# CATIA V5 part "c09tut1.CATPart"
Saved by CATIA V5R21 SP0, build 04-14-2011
Part number: c09_tut1
Bounding box of the stored display mesh (mm): x -75 to 138.5, y -40 to 40, z 0 to 100
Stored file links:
  D:\CATIA V5R21 E-RESOURCES\CATIA-V5R21\catia-v5r21-prt\c09-catia-v5r20-prt\c09-catia-v5r21-tut01.CATPart
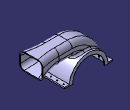
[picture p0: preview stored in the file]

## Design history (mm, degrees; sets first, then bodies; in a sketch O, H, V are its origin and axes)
Body1 (main body)
  Sketch1 on zx-plane, origin (0, 0, 0), H (-1, 0, 0), V (0, 0, 1)
    arc A1 centre (0, 0) radius 60 from (60, 0) to (-60, 0) ccw
    point P1 (-60, 0)
    point P2 (60, 0)
    line L1 (-60, 0) -> (60, 0)
    radius A1 = 60
    coincidence: P1 H, P2 H
    horizontal: L1 H
  Pad1: profile Sketch1, direction (0, 1, 0), length 40, mirrored extent
  Sketch2 on zx-plane, origin (0, 0, 0), H (-1, 0, 0), V (0, 0, 1)
    point P1 (-81.5, 100)
    line L1 (-81.5, 100) -> (-40, 100)
    arc A1 centre (-40, 0) radius 100 from (-40, 100) to (60, 0) cw
    point P4 (60, 0)
    reference projected arc E1 centre (0, 0) radius 60 from (60, 0) to (-60, 0) ccw from edge [face of Pad1 from Sketch1.A1 | end face of Pad1]
    reference projected arc E2 centre (0, 0) radius 60 from (60, 0) to (-60, 0) ccw from edge [face of Pad1 from Sketch1.A1 | end face of Pad1]
    radius A1 = 100
    distance V P1 = 81.5
    distance H L1 = 100
    horizontal: L1 H
    tangency: A1 L1, A1 E2
    coincidence: P4 E1
  Plane1: type Normal, Curve Sketch2, RefPoint Sketch2.P1
  Sketch3 on Plane1, origin (81.5, 0, 0), H (0, 1, 0), V (0, 0, 1)
    line L1 (-28.75, 100) -> (28.75, 100)
    line L2 (28.75, 100) -> (28.75, 58)
    line L3 (28.75, 58) -> (-28.75, 58)
    line L4 (-28.75, 58) -> (-28.75, 100)
    reference projected point E1 (0, 100) from Sketch2.P1
    reference projected point E2 (0, 100) from Sketch2.P1
    length L1 = 57.5
    length L2 = 42
    distance E1 L4 = 28.75
    horizontal: L1 H, L3 H
    vertical: L2 V, L4 V
    coincidence: L1 E2
  Rib1: profile Sketch3, centre curve Sketch2
  Plane2: type Offset, RefPlane face of Rib1, Offset 57, reversed
  Sketch4 on Plane2, origin (138.5, 0, 0), H (0, -1, 0), V (0, 0, 1)
    line L1 (36.25, 100) -> (36.25, 47.5)
    line L2 (36.25, 47.5) -> (-36.25, 47.5)
    line L3 (-36.25, 47.5) -> (-36.25, 100)
    line L4 (-36.25, 100) -> (36.25, 100)
    length L3 = 52.5
    distance V L3 = 36.25
    distance L3 L1 = 72.5
    distance H L4 = 100
    horizontal: L2 H
    vertical: L1 V, L3 V
  Loft1: solid, Sections ({boundary Boundary {extract ExtractElem face of Rib1}}; Sketch4), StartFace face of Rib1
  Fillet1: radius 15, on edge [face of Loft1 | face of Rib1]; edge [face of Rib1 | face of Rib1] (x8); edge [face of Loft1 | face of Loft1] (x2); edge [face of Rib1 | face of Loft1]
  Shell1: ExtOffset 0, Face (face of Loft1; face of Rib1), IntOffset 2.5
  Fillet2: radius 5, on edge [face of Pad1 from Sketch1.A1 | face of Fillet1]; edge [face of Shell1 | face of Shell1]
  Sketch5 on end face of Pad1, origin (0, 40, 0), H (-1, 0, 0), V (0, 0, 1)
    arc A1 centre (0, 0) radius 50 from (50, 0) to (-50, 0) ccw
    point P1 (-50, 0)
    point P2 (50, 0)
    line L1 (-50, 0) -> (50, 0)
    radius A1 = 50
    coincidence: P1 H, P2 H
    horizontal: L1 H
  Pocket1: profile Sketch5, direction (0, -1, 0), through (limit type 6)
  Sketch6 on start face of Pad1, origin (0, -40, 0), H (1, 0, 0), V (0, 0, 1)
    arc A1 centre (0, 0) radius 15 from (15, 0) to (-15, 0) ccw
    point P1 (15, 0)
    point P2 (-15, 0)
    line L1 (-15, 0) -> (15, 0)
    radius A1 = 15
    coincidence: P1 H, P2 H
    horizontal: L1 H
  Pocket2: profile Sketch6, direction (0, 1, 0), through (limit type 6)
  Sketch7 on end face of Pad1, origin (0, 40, 0), H (-1, 0, 0), V (0, 0, 1)
    line L1 (59.8665, 4) -> (75, 4)
    line L2 (60, 0) -> (75, 0)
    line L3 (75, 4) -> (75, 0)
    projected arc E1 centre (0, 0) radius 60 from (60, 0) to (-60, 0) ccw from edge [face of Pad1 from Sketch1.A1 | end face of Pad1]
    projected arc E2 centre (0, 0) radius 60 from (60, 0) to (59.8665, 4) ccw from edge [face of Pad1 from Sketch1.A1 | end face of Pad1]
    point P5 (59.8665, 4)
    length L3 = 4
    distance V L3 = 75
    horizontal: L1 H, L2 H
    vertical: L3 V
    coincidence: E1 P5
  Pad2: profile Sketch7, direction (0, -1, 0), up to start face of Pad1
  Mirror1: of Pad2, about yz-plane
  Sketch8 on face of Pad2 from Sketch7.L1, origin (-64.0831, -0.1557, 4), H (1, 0, 0), V (0, 1, 0)
    point P1 (-3.4169, -29.8443)
    reference projected line E1 (-10.9169, 40.1557) -> (-10.9169, -39.8443) from edge [face of Pad2 from Sketch7.L3 | face of Pad2 from Sketch7.L1]
    reference projected line E2 (4.2165, -39.8443) -> (-10.9169, -39.8443) from edge [face of Pad2 from Sketch7.L1 | face of Pad1]
    distance P1 E1 = 7.5
    distance E2 P1 = 10
  Hole1: placed by Sketch8, at (-67.5, -30, 4) direction (0, 0, -1), diameter 4, depth 10
  RectPattern1: of Hole1, direction 1 instances 4, spacing 20, along edge [face of Pad2 from Sketch7.L3 | face of Pad2 from Sketch7.L1] reversed, direction 2 instances 2, spacing 135, along edge [face of Rib1 | face of Pad1] reversed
